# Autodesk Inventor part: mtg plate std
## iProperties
Created: 2010-10
Part Number: mtg plate std
Document SubType Name: Modeling
Designer: Administrator
Density: 7.85 g/cm^3
Material: Steel
Mass: 161.514 g
Surface Area: 127.526 cm^2
Volume: 20.575 cm^3
Author: Administrator
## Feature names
1. Base1
